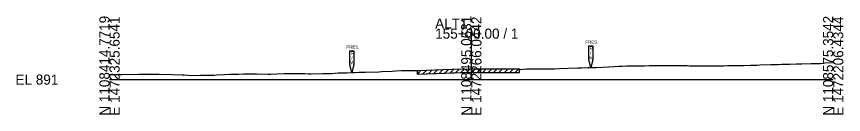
# Model space of a CAD drawing. Extents: x -26 to 2203, y -10 to 19568.
# Drawn here: x -25.7 to 202.8, y 16990.3 to 17017.5 of the extents above; entities that cross this region are included whole.
import ezdxf

# ---------------------------------------------------------------- set-up
doc = ezdxf.new("R2010")
doc.units = 0
for name, color, linetype in [('RD_GPK_XS_Cell', 7, 'Continuous'), ('RD_XS_ExGround', 7, 'Continuous'), ('RD_XS_ExPaveRet', 7, 'Continuous'), ('RD_XS_ExRW', 7, 'Continuous')]:
    doc.layers.add(name, color=color, linetype=linetype)

msp = doc.modelspace()

# ---------------------------------------------------------------- linework, layer by layer
at = {"layer": 'RD_GPK_XS_Cell'}
for p, q in [((100, 17000), (100, 17014.15)), ((0, 17000), (100, 17000)), ((100, 17000), (200, 17000))]:
    msp.add_line(p, q, dxfattribs=at)
at = {"layer": 'RD_XS_ExGround'}
msp.add_lwpolyline([(0, 17001.4), (1.35, 17001.42), (3.4, 17001.44), (8.12, 17001.5), (10.46, 17001.53), (13.68, 17001.49), (17.44, 17001.37), (20.09, 17001.31), (20.52, 17001.29), (22.77, 17001.11), (25.12, 17001.19), (28.91, 17001.25), (29.55, 17001.29), (31.79, 17001.41), (33.29, 17001.5), (33.81, 17001.51), (35.66, 17001.52), (37.03, 17001.56), (38.84, 17001.58), (40.76, 17001.56), (43.88, 17001.52), (44.5, 17001.53), (46.38, 17001.64), (48.23, 17001.65), (48.91, 17001.65), (50.67, 17001.67), (51.97, 17001.69), (52.81, 17001.7), (53.94, 17001.66), (54.95, 17001.63), (55.71, 17001.63), (58.97, 17001.67), (59.44, 17001.68), (61.39, 17001.73), (63.18, 17001.84), (64.01, 17001.88), (65.68, 17001.92), (66.92, 17001.96), (67.82, 17001.98), (69.04, 17002.03), (70.65, 17002.08), (74.39, 17002.16), (75.3, 17002.21), (78.13, 17002.37), (79.1, 17002.42), (80.69, 17002.5), (82.92, 17002.55), (85.13, 17002.53), (94.66, 17002.85), (99.5, 17003.01), (100, 17003.01), (109.87, 17002.97), (113.18, 17002.99), (113.54, 17002.83), (115.23, 17002.95), (117.14, 17002.95), (119.37, 17002.99), (121.43, 17002.96), (122.96, 17002.99), (124.4, 17003.04), (126.7, 17003.15), (129.43, 17003.24), (130.44, 17003.27), (132.15, 17003.32), (134.46, 17003.35), (137.91, 17003.52), (139.5, 17003.62), (140.73, 17003.7), (141.64, 17003.74), (142.87, 17003.78), (144.53, 17003.79), (145.02, 17003.79), (145.38, 17003.8), (147.83, 17003.86), (149.12, 17003.9), (149.56, 17003.9), (151.45, 17003.89), (152.85, 17003.89), (154.6, 17003.89), (155.74, 17003.88), (156.59, 17003.88), (157.88, 17003.88), (159.63, 17003.87), (160.33, 17003.86), (162.17, 17003.85), (164.06, 17003.84), (164.66, 17003.83), (167.8, 17003.8), (168.61, 17003.8), (169.69, 17003.85), (170.75, 17003.88), (171.54, 17003.88), (174.73, 17003.92), (175.27, 17003.94), (177.18, 17004.01), (179.01, 17004.03), (179.76, 17004.05), (182.75, 17004.15), (183.62, 17004.18), (184.79, 17004.22), (185.76, 17004.25), (186.48, 17004.27), (187.91, 17004.28), (189.82, 17004.37), (190.22, 17004.38), (191.35, 17004.39), (193.95, 17004.42), (194.34, 17004.42), (194.86, 17004.44), (196.48, 17004.51), (197.69, 17004.61), (200, 17004.72)], dxfattribs=at)
at = {"layer": 'RD_XS_ExPaveRet'}
for p, q in [((94.13, 17001.83), (95.16, 17002.86)), ((95.63, 17001.88), (96.67, 17002.91)), ((97.13, 17001.93), (98.17, 17002.97)), ((98.63, 17001.98), (99.66, 17003.01)), ((100.13, 17002.01), (101.13, 17003.01)), ((101.63, 17002.01), (102.63, 17003)), ((103.13, 17002), (104.13, 17002.99)), ((104.63, 17001.99), (105.63, 17002.99)), ((106.13, 17001.99), (107.13, 17002.98)), ((107.63, 17001.98), (108.63, 17002.98)), ((109.13, 17001.98), (110.13, 17002.97)), ((110.63, 17001.97), (111.64, 17002.98)), ((112.13, 17001.98), (113.1, 17002.95)), ((113.18, 17002.99), (113.18, 17001.99)), ((113.18, 17002.99), (113.18, 17001.99)), ((85.13, 17001.54), (86.15, 17002.57)), ((85.13, 17001.54), (85.13, 17002.53)), ((85.13, 17002.53), (85.13, 17001.53)), ((85.13, 17001.53), (94.66, 17001.85)), ((85.13, 17001.54), (85.32, 17001.54)), ((85.32, 17001.54), (95.22, 17001.87)), ((86.63, 17001.59), (87.66, 17002.62)), ((88.13, 17001.63), (89.16, 17002.67)), ((89.63, 17001.68), (90.66, 17002.71)), ((91.13, 17001.73), (92.16, 17002.76)), ((92.63, 17001.78), (93.66, 17002.81)), ((94.66, 17001.85), (99.5, 17002.01)), ((95.22, 17001.87), (99.5, 17002.02)), ((99.5, 17002.02), (100, 17002.01)), ((100, 17002.01), (110.09, 17001.97)), ((100, 17002.01), (109.87, 17001.97)), ((109.88, 17001.97), (113.18, 17001.99)), ((110.09, 17001.97), (113.02, 17001.98)), ((113.02, 17001.98), (113.18, 17001.92)), ((113.18, 17001.99), (113.18, 17001.98))]:
    msp.add_line(p, q, dxfattribs=at)
at = {"layer": 'RD_XS_ExRW'}
for points in [[(66.45, 17007.97), (67.55, 17007.97), (67.55, 17004.14), (67, 17001.96), (66.45, 17004.14)], [(132.45, 17009.34), (133.55, 17009.34), (133.55, 17005.51), (133, 17003.32), (132.45, 17005.51)]]:
    msp.add_lwpolyline(points, close=True, dxfattribs=at)

# ---------------------------------------------------------------- texts
at = {"layer": 'RD_GPK_XS_Cell'}
for s, p in [('N 1108414.7719', (0, 16990)), ('E 1472325.6541', (2.8, 16990)), ('N 1108495.0631', (100, 16990)), ('E 1472266.0442', (102.8, 16990)), ('N 1108575.3542', (200, 16990)), ('E 1472206.4344', (202.8, 16990))]:
    msp.add_text(s, height=2.8, rotation=90, dxfattribs=at).set_placement(p)
for s, p in [('ALT1', (90, 17014.15)), ('155+00.00 / 1', (90, 17011.35)), ('EL 891', (-26, 16998.6))]:
    msp.add_text(s, height=2.8, dxfattribs=at).set_placement(p)
at = {"layer": 'RD_XS_ExRW'}
for s, p in [('PRES.', (131.45, 17009.97)), ('PRES.', (65.45, 17008.6)), ('R', (66.71, 17006.88)), ('R', (132.71, 17008.25)), ('/', (132.83, 17006.94)), ('W', (66.53, 17004.26)), ('/', (66.83, 17005.57)), ('W', (132.53, 17005.62))]:
    msp.add_text(s, height=0.875, dxfattribs=at).set_placement(p)

doc.saveas('drawing.dxf')
